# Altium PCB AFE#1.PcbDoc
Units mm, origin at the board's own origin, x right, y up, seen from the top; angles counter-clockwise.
Board outline 43.03 x 43.18 mm, 4 copper layers (Top Layer, Int1 (GND), Int2 (GND), Bottom Layer), stack 1.56 mm thick; 65 components, 51 nets, 213 pads, 60 vias.
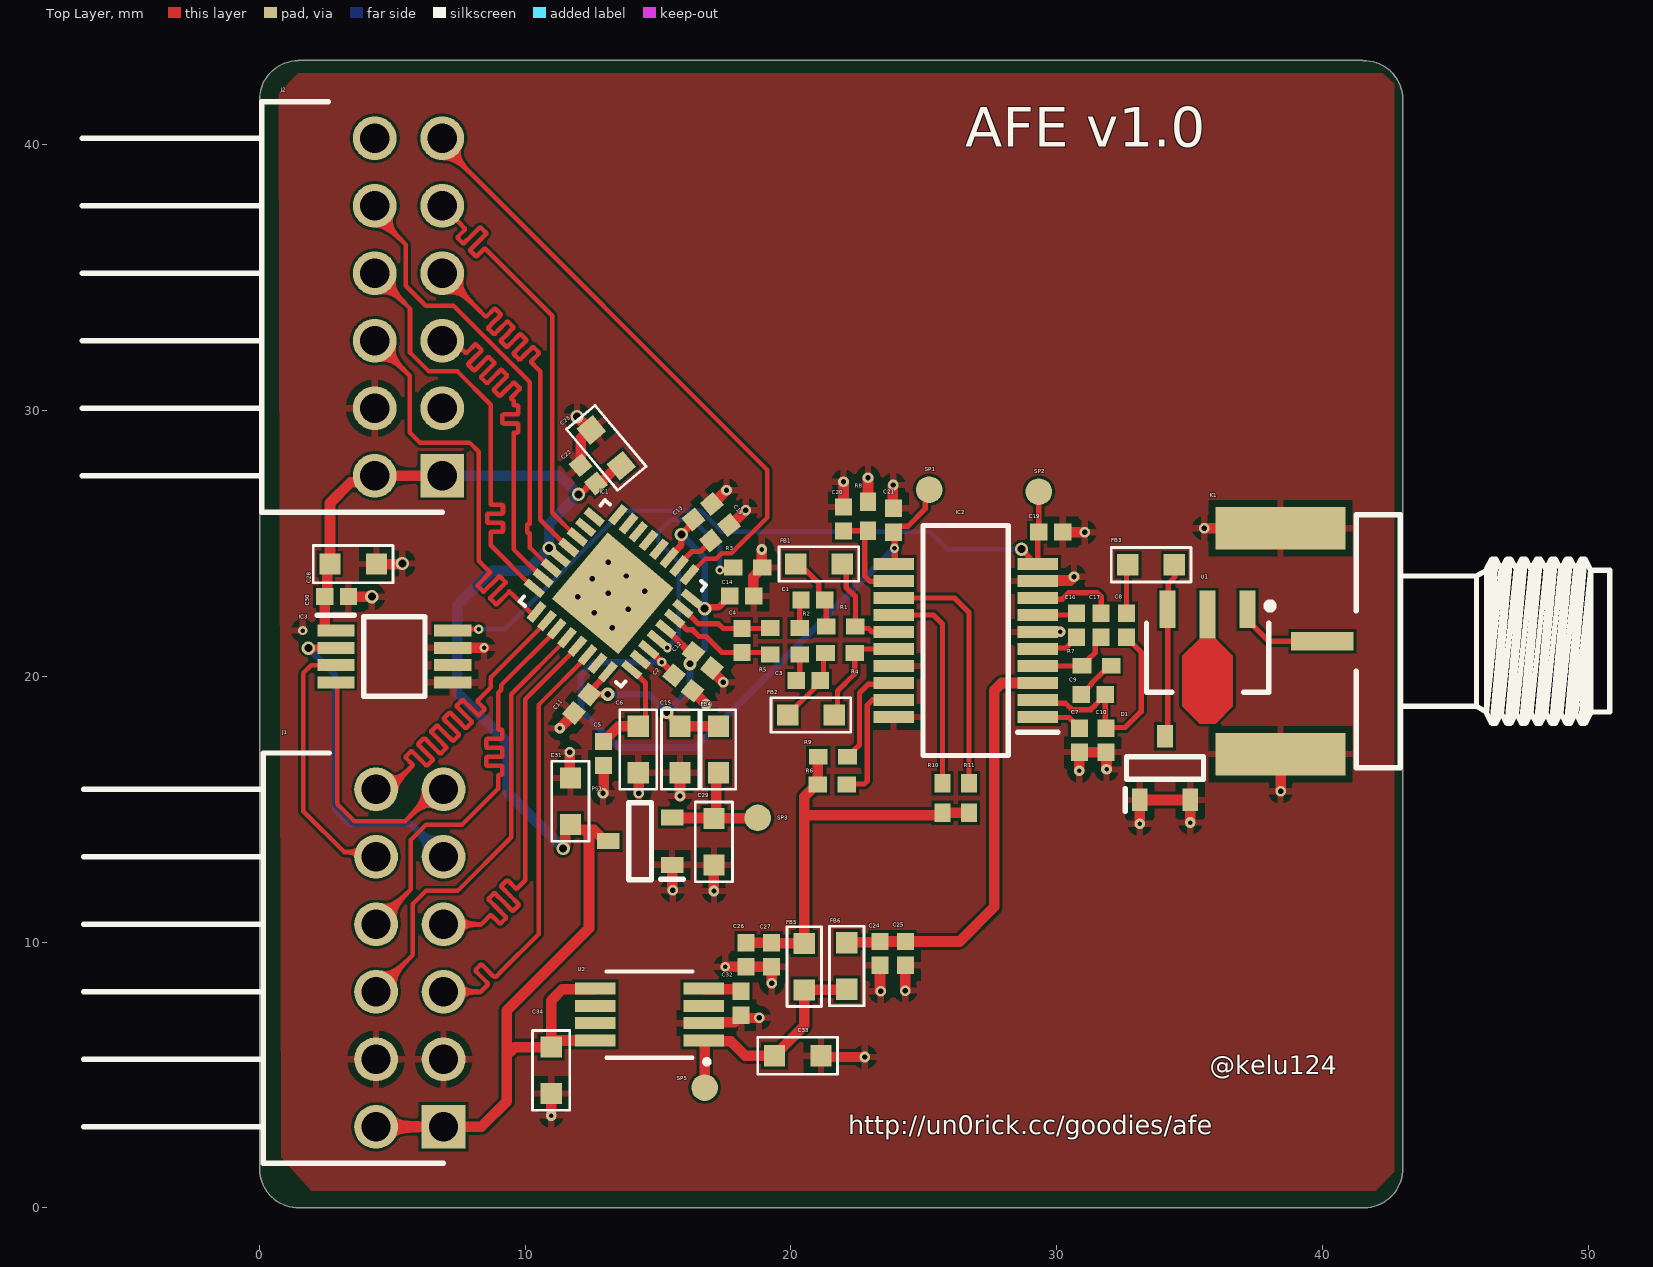
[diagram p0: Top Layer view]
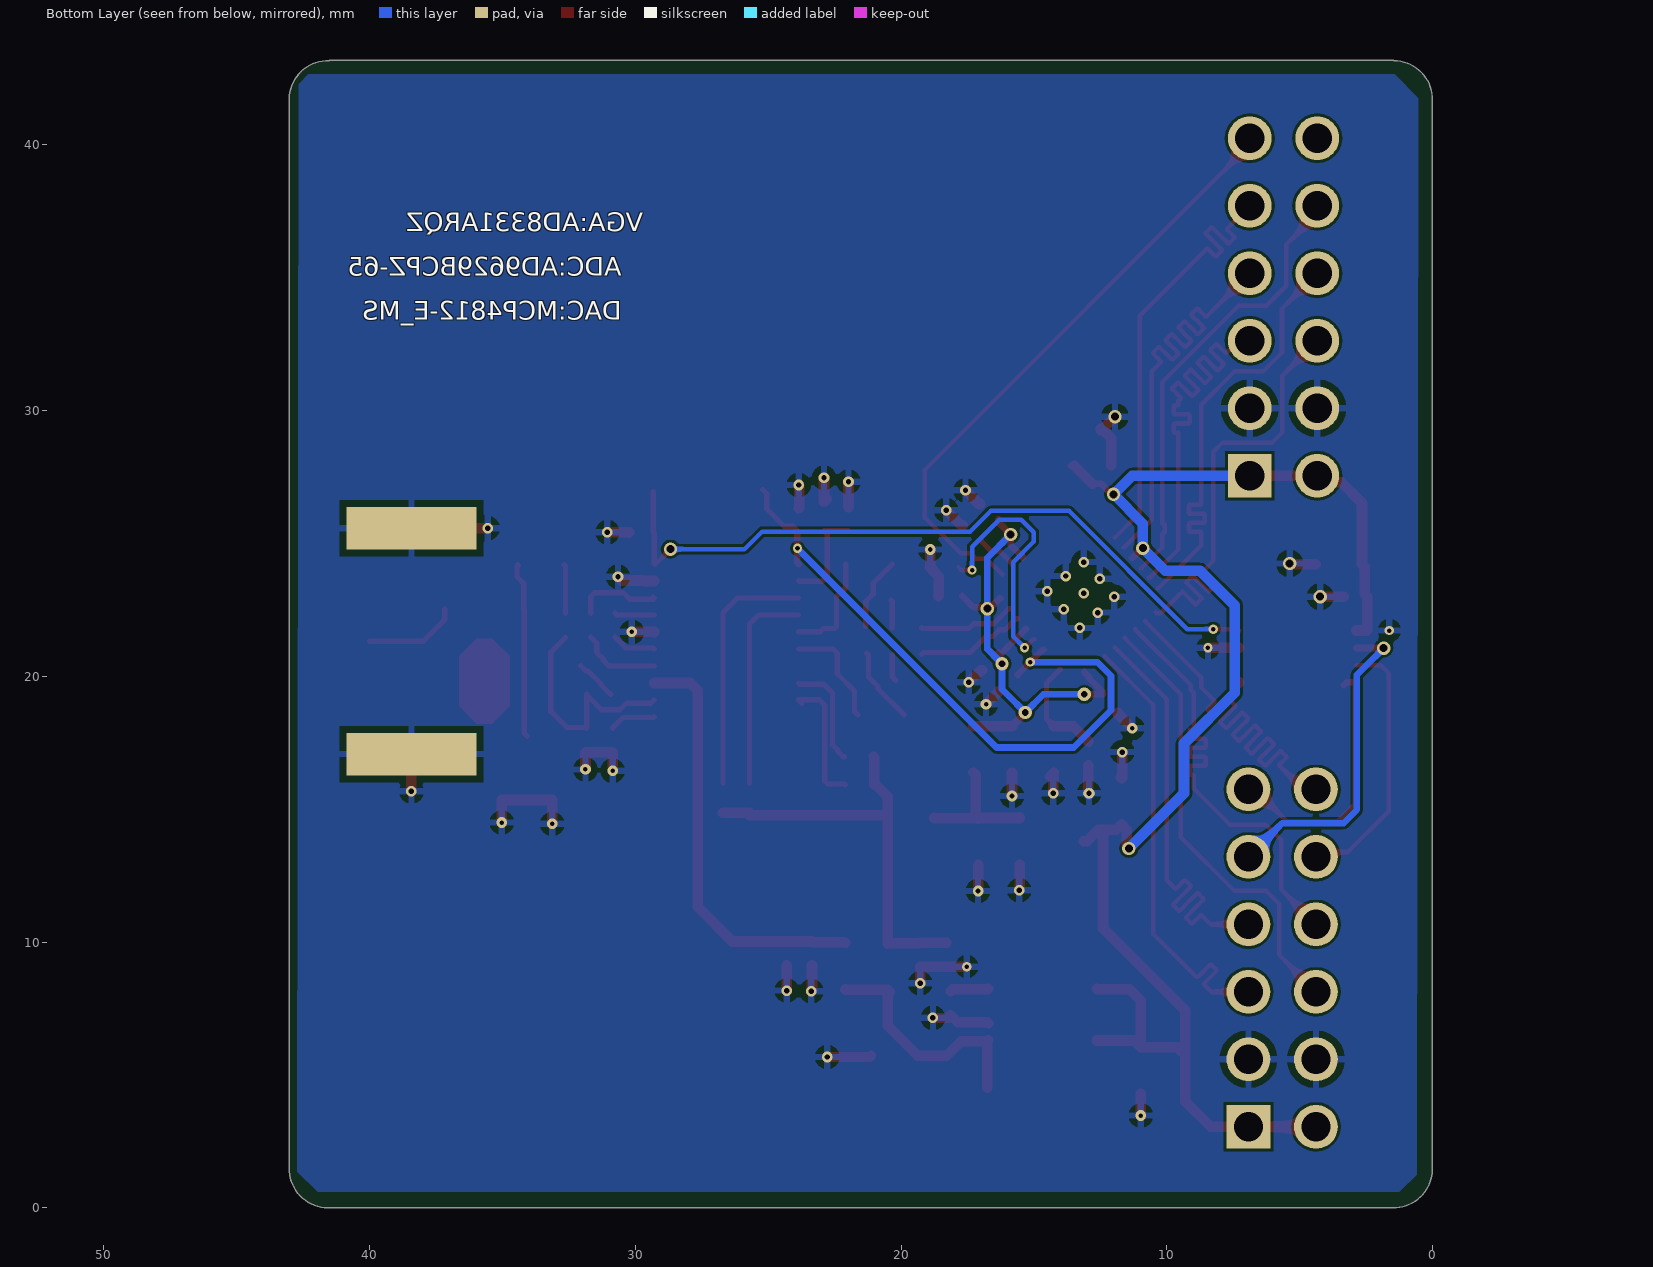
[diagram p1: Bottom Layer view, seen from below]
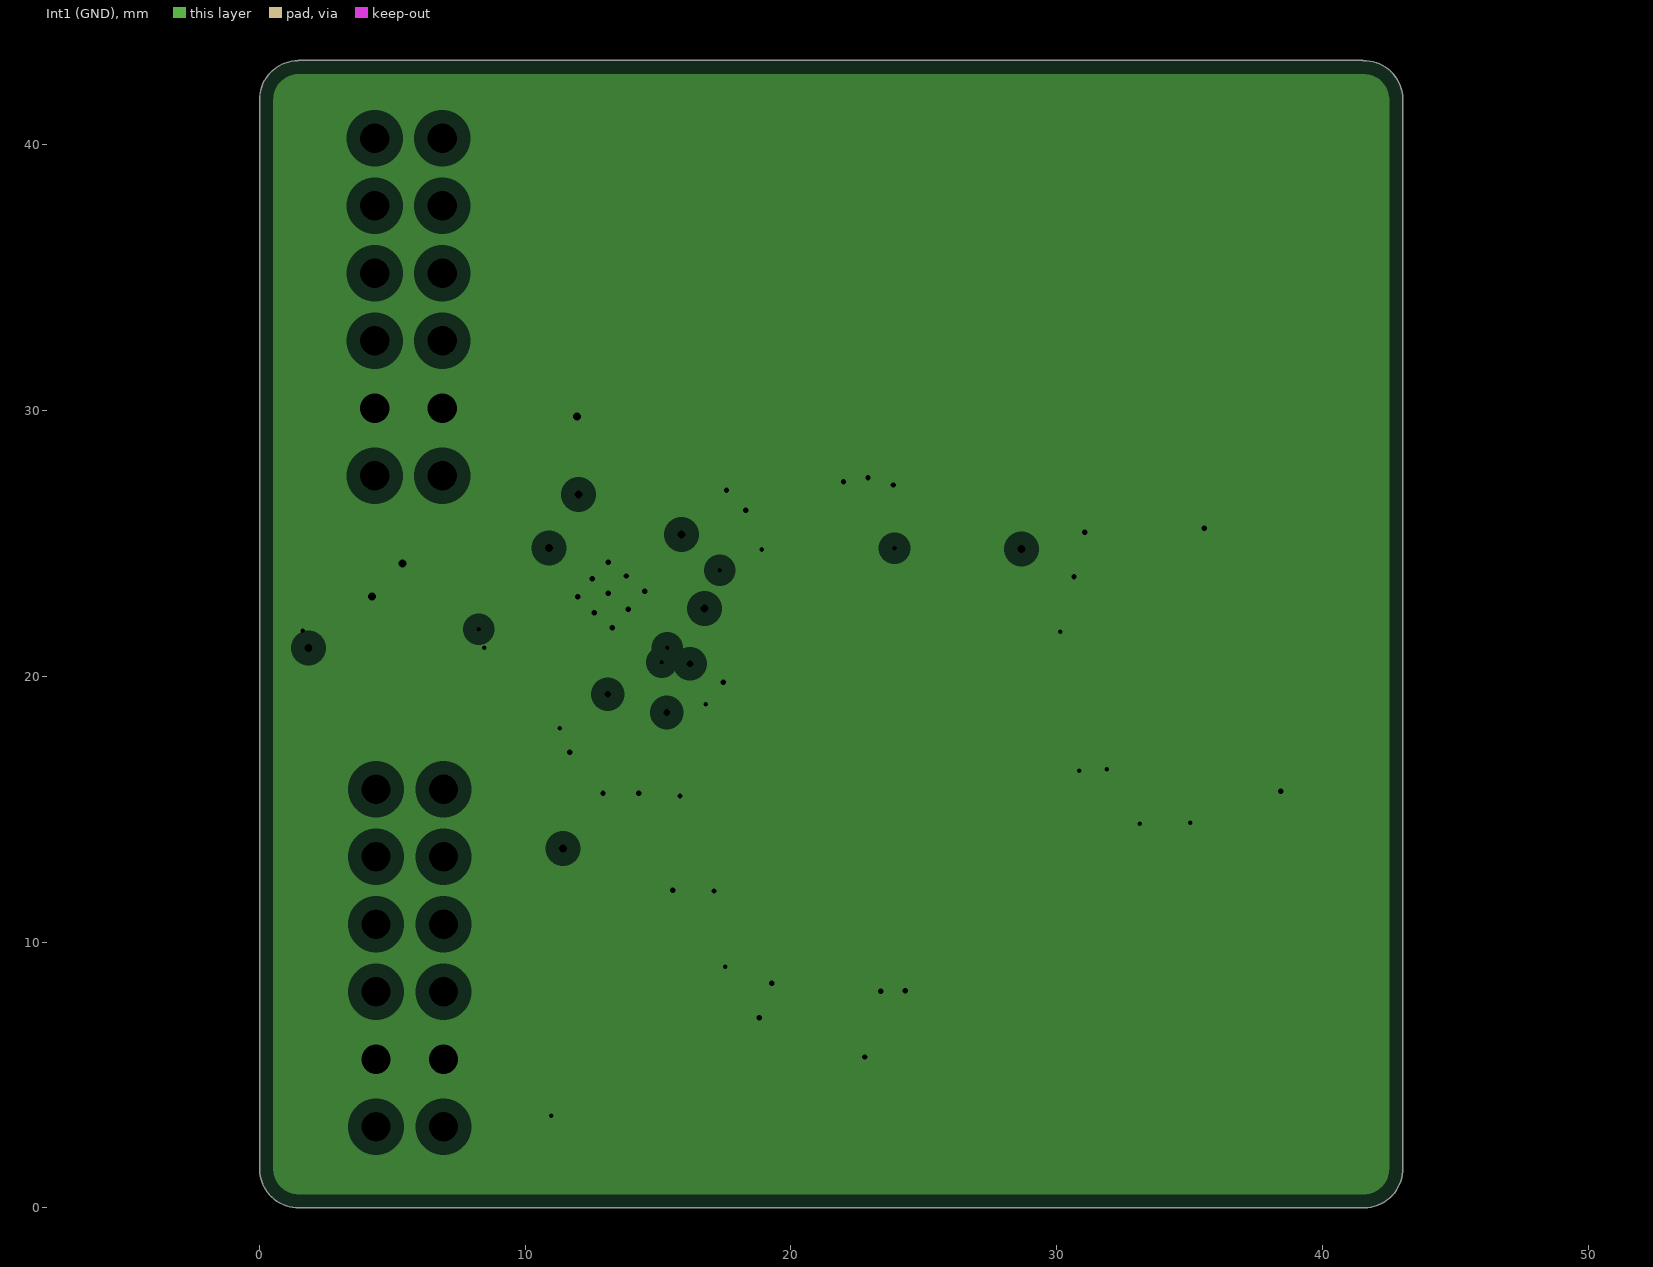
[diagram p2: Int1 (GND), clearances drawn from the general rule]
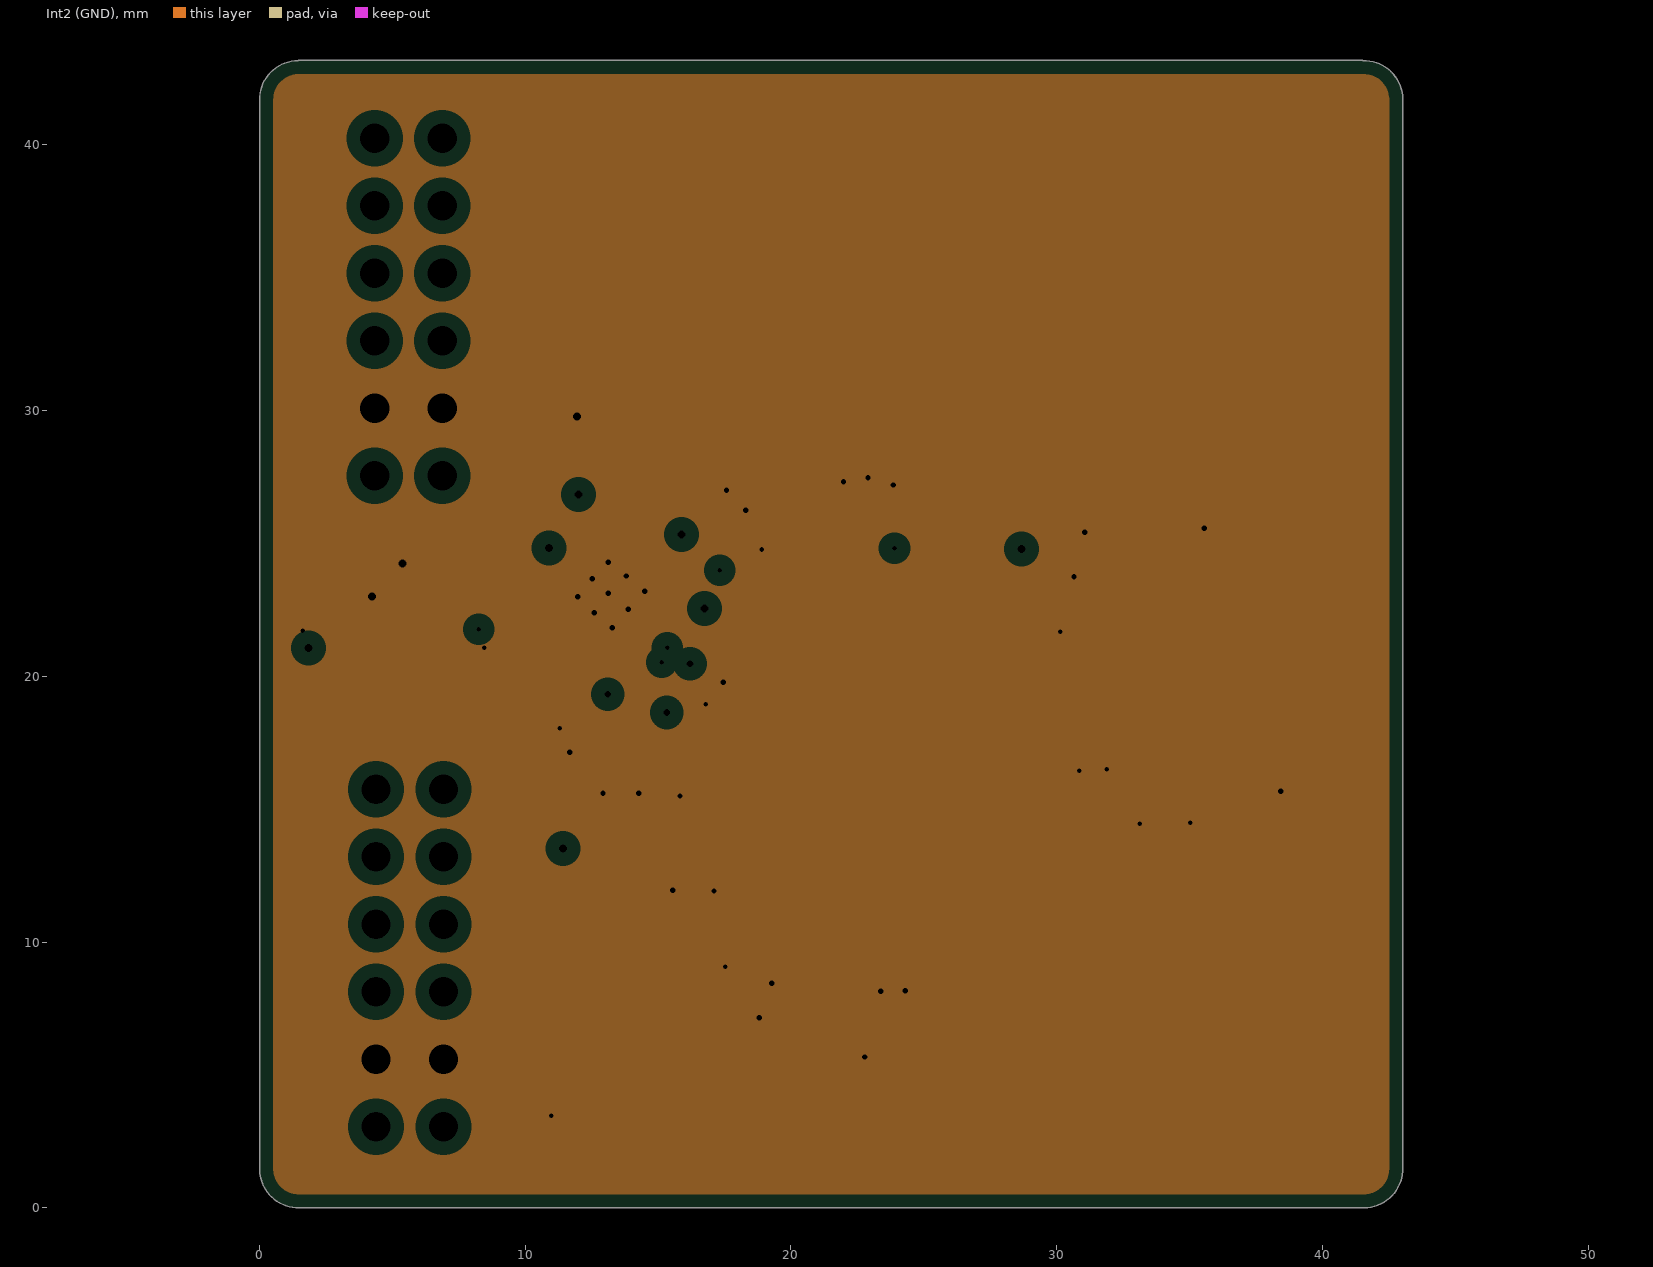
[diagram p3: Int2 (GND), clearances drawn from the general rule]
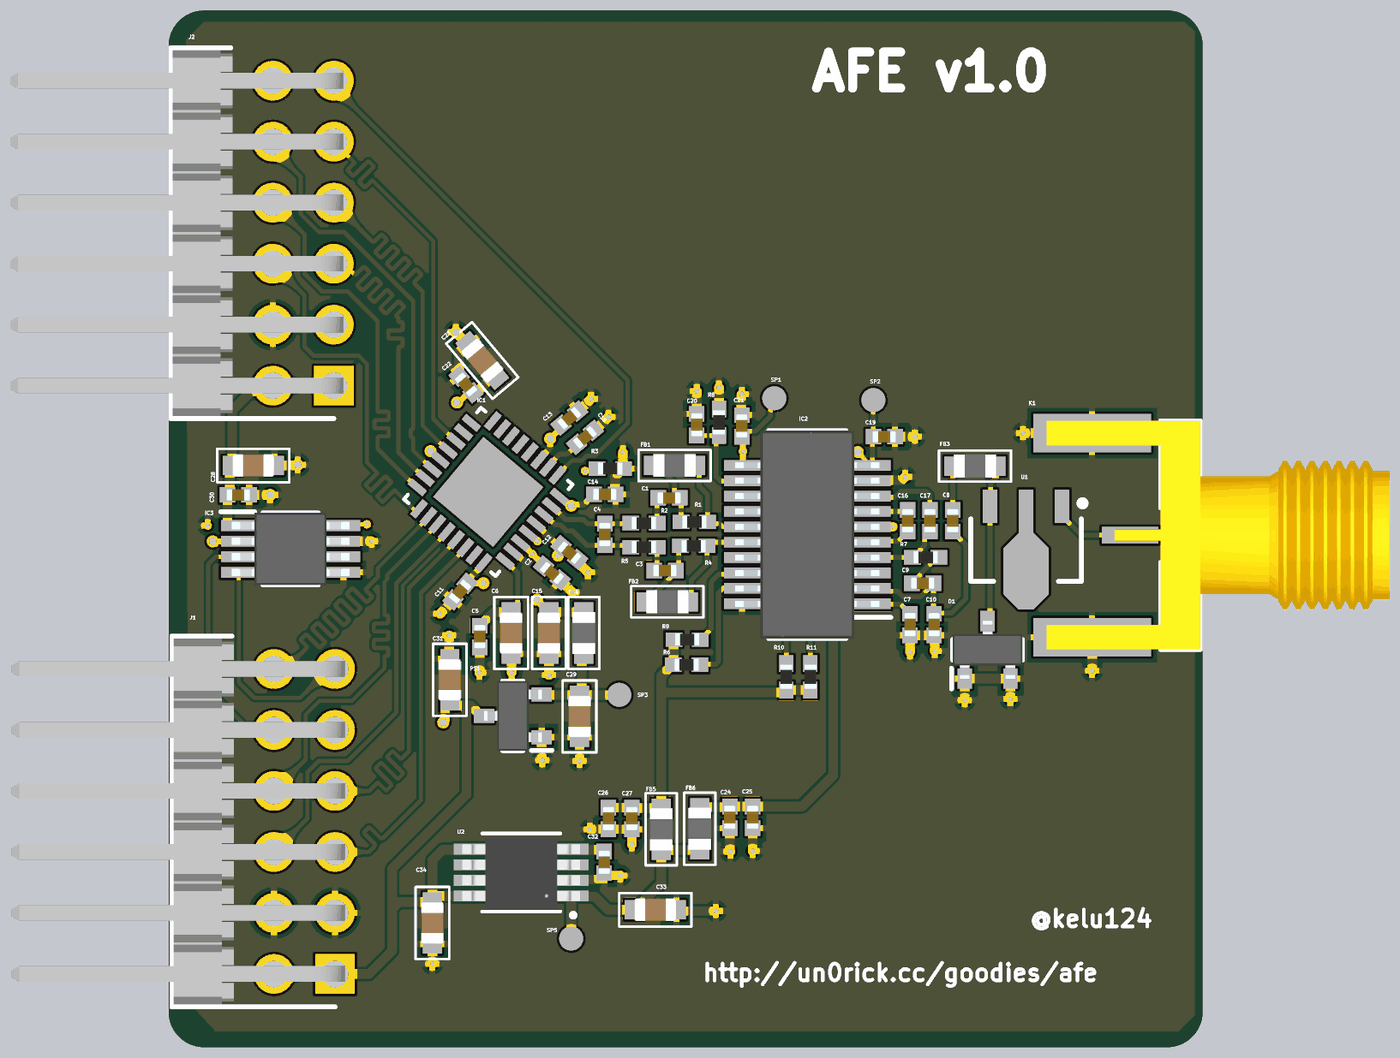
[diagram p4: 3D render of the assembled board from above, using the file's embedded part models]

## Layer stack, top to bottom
Top Solder: solder mask 0.0254, SM-001, Dk 4
Top Layer: signal copper 0.035
Dielectric 1: prepreg 0.11, PP-017, Dk 4.3
Int1 (GND): plane copper 0.035, net GND
Dielectric 3: core 1.2, Core-039, Dk 4.8
Int2 (GND): plane copper 0.035, net GND
Dielectric 5: prepreg 0.11, PP-017, Dk 4.3
Bottom Layer: signal copper 0.035
Bottom Solder: solder mask 0.0254, SM-001, Dk 4

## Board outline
0,1.45 0,41.675 cw(c1.475,41.7) 1.45,43.175 1.45,43.18 41.525,43.18 41.525,43.175 cw(c41.55,41.7) 43.025,41.725 43.025,1.5 cw(c41.55,1.475) 41.575,0 41.55,0 1.5,0 cw(c1.475,1.475)

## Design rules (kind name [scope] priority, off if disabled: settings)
Clearance [All] p1: gap=0.1 ignorepadtopadclearanceinfootprint=TRUE
ComponentClearance [All] p1: gap=0 collisioncheckmode=3 verticalgap=0 showdistances=FALSE
MatchedLengths "Schematic Matched Net Lengths" [InNetClass('Data')] p1: tolerance=0.508 checknetsindiffpair=FALSE checkdiffpairvsdiffpair=TRUE checkxsignals=TRUE checkothers=TRUE
PlaneClearance [All] p1: clearance=0.508
PlaneConnect [All] p1: planeconnectstyle=Relief reliefexpansion=0.508 reliefentries=4 reliefconductorwidth=0.254 reliefairgap=0.254
PolygonConnect [All] p1: connectstyle=Relief reliefconductorwidth=0.254 reliefentries=4 polygonreliefangle="90 Angle" airgapwidth=0.254
RoutingVias [All] p1: holewidth=0.2 width=0.4 viastyle="Through Hole" minholewidth=0.15 minwidth=0.3 maxholewidth=0.4 maxwidth=0.8
SilkToSilkClearance [All] p1: silktosilkclearance=0
SolderMaskExpansion [All] p1: expansion=0.102
UnRoutedNet [All] p1: checkbadconnections=TRUE
Width [All] p1: maxlimit=0.4 minlimit=0.15 preferedwidth=0.2
25 further rules are at their usual default settings.

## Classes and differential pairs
net class Data: D0 D1 D2 D3 D4 D5 D6 D7 D8 D9 DCO

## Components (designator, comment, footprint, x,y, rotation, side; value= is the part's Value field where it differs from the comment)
C1 "cap0402" 0402_C 20.825,22.875 r0 top value=100n
C2 "cap0402" 0402_C 15.95,19.75 r320 top value=100n
C3 "cap0402" 0402_C 20.65,19.85 r0 top value=100n
C4 "cap0402" 0402_C 18.15,21.35 r270 top value=18pf
C5 "cap0402" 0402_C 12.95,17.1 r90 top value=100n
C6 "cap0603" "SM0603 _3D_cap" 14.25,17.25 r90 top value=1u
C7 "cap0402" 0402_C 30.85,17.6 r90 top value=100n
C8 "cap0402" 0402_C 32.625,21.925 r270 top value=100n
C9 "cap0402" 0402_C 31.375,19.325 r0 top value=18n
C10 "cap0402" 0402_C 31.85,17.6 r90 top value=22pF
C11 "cap0402" 0402_C 12.125,18.975 r230 top value=100n
C12 "cap0402" 0402_C 16.675,20.6 r320 top value=100n
C13 "cap0402" 0402_C 16.675,26.2 r40 top value=100n
C14 "cap0402" 0402_C 18.15,23.025 r0 top value=100n
C15 "cap0402" "SM0603 _3D_cap" 15.825,17.25 r270 top value=10u
C16 "cap0402" 0402_C 30.75,21.925 r270 top value=100n
C17 "cap0402" 0402_C 31.675,21.925 r270 top value=100n
C18 "cap0402" 0402_C 17.325,25.4 r40 top value=100n
C19 "cap0402" 0402_C 29.775,25.425 r180 top value=1n
C20 "cap0402" 0402_C 21.975,25.925 r270 top value=100n
C21 "cap0402" 0402_C 23.85,25.875 r90 top value=100n
C22 "cap0402" 0402_C 12.375,27.6 r130 top value=100n
C23 "cap0603" "SM0603 _3D_cap" 13.05,28.6 r130 top value=10u
C24 "cap0402" 0402_C 23.35,9.575 r90 top value=1nf
C25 "cap0402" 0402_C 24.3,9.575 r90 top value=100nf
C26 "cap0402" 0402_C 18.3,9.525 r90 top value=1nf
C27 "cap0402" 0402_C 19.275,9.525 r90 top value=100nf
C28 "cap0603" "SM0603 _3D_cap" 3.525,24.225 r0 top value=10u
C29 "cap0603" "SM0603 _3D_cap" 17.1,13.775 r270 top value=4.7u
C30 "cap0402" 0402_C 2.9,23 r0 top value=100n
C31 "cap0603" "SM0603 _3D_cap" 11.7,15.3 r270 top value=4.7u
C32 "cap0402" 0402_C 18.125,7.7 r90 top value=470p
C33 "cap0603" "SM0603 _3D_cap" 20.25,5.725 r0 top value=1u
C34 "cap0603" "SM0603 _3D_cap" 10.975,5.175 r270 top value=1u
D1 "BAV99-7-F" SOT95P240X120-3N 34.075,16.55 r90 top
FB1 "75R@100MHz" SM0603_3D_res 21.05,24.225 r180 top
FB2 "75R@100MHz" SM0603_3D_res 20.75,18.55 r180 top
FB3 "75R@100MHz" SM0603_3D_res 33.55,24.2 r180 top
FB4 "75R@100MHz" SM0603_3D_res 17.275,17.25 r270 top
FB5 "75R@100MHz" SM0603_3D_res 20.5,9.075 r270 top
FB6 "75R@100MHz" SM0603_3D_res 22.1,9.1 r90 top
IC1 "AD9629BCPZ-65" QFN50P500X500X100-33N 13.3,23.125 r230 top
IC2 "AD8331ARQZ" SOP64P600X175-20N 26.575,21.35 r180 top
IC3 "MCP4812-E_MS" SOP65P490X110-8N 5.075,20.75 r0 top
J1 "90122-0126" HDRRA12W65P254_2X6_1516X250X615P 6.925,3.05 r90 top
J2 "90122-0126" HDRRA12W65P254_2X6_1516X250X615P 6.875,27.55 r90 top
K1 "SMA_Edge" AMPHENOL_132357-11 40,21.325 r180 top
PS1 "AP2127N-1.8TRG1" SOT89P240X110-3N 14.325,13.8 r180 top
R1 "100R" 0402_R 21.875,21.875 r180 top value=10k
R2 "18R" 0402_R 19.775,21.825 r180 top
R3 "10K" 0402_R 18.375,24.1 r180 top value=10k
R4 "100R" 0402_R 21.85,20.875 r180 top value=10k
R5 "18R" 0402_R 19.775,20.825 r180 top
R6 "10k" 0402_R 21.55,15.925 r0 top
R7 "280" 0402_R 31.5,20.4 r0 top
R8 "12k" 0402_R 22.9,26.025 r90 top
R9 "10k" 0402_R 21.575,16.975 r0 top
R10 "10k" 0402_R 25.7,15.425 r90 top
R11 "10k" 0402_R 26.7,15.425 r90 top
SP1 "SolderPad D1mm_round" "SolderPad_D1mm _round" 25.2,27.025 r90 top value="\"VCM\""
SP2 "SolderPad D1mm_round" "SolderPad_D1mm _round" 29.325,26.95 r90 top value="\"DG\""
SP3 "SolderPad D1mm_round" "SolderPad_D1mm _round" 18.75,14.675 r90 top value="\"+1.8V\""
SP5 "SolderPad D1mm_round" "SolderPad_D1mm _round" 16.75,4.525 r90 top value="\"+5V\""
U1 "T/R switch" SOT89-150P409X160-3N 35.675,20.725 r270 top
U2 "TC1107-5.0VUA" MSOP8_MC_MCH_ 14.675,7.275 r180 top

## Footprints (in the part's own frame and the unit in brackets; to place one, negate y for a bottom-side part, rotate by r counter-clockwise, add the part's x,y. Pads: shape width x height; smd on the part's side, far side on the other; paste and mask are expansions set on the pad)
0402_C [mm]
  rect 0.65x0.64 smd: 1(-0.45,0) 2(0.45,0)
  body extent -0.5,-0.25 0.5,0.25, height 0.56
0402_R [mm]
  rect 0.7x0.6 smd: 1(-0.55,0) 2(0.55,0)
  body extent -0.5,-0.25 0.5,0.25, height 0.35
AMPHENOL_132357-11 [mm]
  rect 2.35x0.7 smd: 1(0,0)
  rect 4.9x1.6 smd: 2(1.575,4.25) 2(1.575,-4.25)
  rect 4.9x1.6 smd far side: 2(1.575,4.25) 2(1.575,-4.25)
  silkscreen extent -10.81,-4.76 -1.28,4.76, body extent -10.8,-4.76 3.48,4.76, height 4.08
HDRRA12W65P254_2X6_1516X250X615P [mm]
  rect 1.65x1.65 hole 1.1: 1(0,0)
  round 1.65 hole 1.1: 2(0,2.54) 3(2.54,0) 4(2.54,2.54) 5(5.08,0) 6(5.08,2.54) 7(7.62,0) 8(7.62,2.54) 9(10.16,0) 10(10.16,2.54) 11(12.7,0) 12(12.7,2.54)
  silkscreen extent -1.37,0 14.07,13.54, body extent -1.27,-0.4 13.97,13.47, height 6.16
MSOP8_MC_MCH_ [mil]
  rect 60x18 smd paste+0 mask+0: 1(-80.5,38.39) 2(-80.5,12.8) 3(-80.5,-12.8) 4(-80.5,-38.39) 5(80.5,-38.39) 6(80.5,-12.8) 7(80.5,12.8) 8(80.5,38.39)
  silkscreen extent -87,-64 64,72, body extent -96,-59 96,59, height 43
QFN50P500X500X100-33N [mil]
  rect 32x12 smd: 1(-94,69) 2(-94,49) 3(-94,30) 4(-94,10) 5(-94,-10) 6(-94,-30) 7(-94,-49) 8(-94,-69) 17(94,-69) 18(94,-49) 19(94,-30) 20(94,-10) 21(94,10) 22(94,30) 23(94,49) 24(94,69)
  rect 12x32 smd: 9(-69,-94) 10(-49,-94) 11(-30,-94) 12(-10,-94) 13(10,-94) 14(30,-94) 15(49,-94) 16(69,-94) 25(69,94) 26(49,94) 27(30,94) 28(10,94) 29(-10,94) 30(-30,94) 31(-49,94) 32(-69,94)
  rect 128x128 smd: 33(0,0)
  silkscreen extent -98,-98 98,98
"SM0603 _3D_cap" [mm]
  rect 0.8x0.8 smd: 1(-0.875,0) 2(0.875,0)
  silkscreen extent -1.5,-0.7 1.5,0.7, body extent -0.87,-0.47 0.88,0.48, height 0.87
SM0603_3D_res [mm]
  rect 0.8x0.8 smd: 1(-0.875,0) 2(0.875,0)
  silkscreen extent -1.5,-0.65 1.5,0.65, body extent -0.87,-0.47 0.88,0.48, height 0.55
"SolderPad_D1mm _round" [mm]
  round 1 smd: 1(0,0)
SOP64P600X175-20N [mm]
  rect 1.52x0.44 smd: 1(-2.715,2.88) 2(-2.715,2.24) 3(-2.715,1.6) 4(-2.715,0.96) 5(-2.715,0.32) 6(-2.715,-0.32) 7(-2.715,-0.96) 8(-2.715,-1.6) 9(-2.715,-2.24) 10(-2.715,-2.88) 11(2.715,-2.88) 12(2.715,-2.24) 13(2.715,-1.6) 14(2.715,-0.96) 15(2.715,-0.32) 16(2.715,0.32) 17(2.715,0.96) 18(2.715,1.6) 19(2.715,2.24) 20(2.715,2.88)
  silkscreen extent -3.47,-4.33 1.61,4.33, body extent -3,-4.33 3,4.33, height 1.75
SOP65P490X110-8N [mm]
  rect 1.4x0.45 smd: 1(-2.2,0.975) 2(-2.2,0.325) 3(-2.2,-0.325) 4(-2.2,-0.975) 5(2.2,-0.975) 6(2.2,-0.325) 7(2.2,0.325) 8(2.2,0.975)
  silkscreen extent -2.9,-1.5 1.15,1.55, body extent -2.45,-1.5 2.45,1.5, height 1.1
SOT89-150P409X160-3N [mm]
  rect 1.4x0.6 smd: 1(-1.8,1.5) 3(-1.8,-1.5)
  rect 1.8x0.6 smd: 2(-1.6,0)
  Top Layer region: -0.7,0.3 -0.05,0.95 1.85,0.95 2.5,0.3 2.5,-0.3 1.85,-0.95 -0.05,-0.95 -0.7,-0.3
  silkscreen extent -2.05,-2.3 1.32,2.48, body extent -1.28,-2.3 1.32,2.3, height 1.6
SOT89P240X110-3N [mm]
  rect 0.85x0.6 smd: 1(-1.2,0.89) 2(-1.2,-0.89) 3(1.2,0)
  silkscreen extent -1.63,-1.45 0.43,1.45, body extent -1.2,-1.45 1.2,1.45, height 1.1
SOT95P240X120-3N [mm]
  rect 0.85x0.6 smd: 1(-1.2,0.95) 2(-1.2,-0.95) 3(1.2,0)
  silkscreen extent -1.63,-1.45 0.43,1.5, body extent -1.2,-1.45 1.2,1.45, height 1.2

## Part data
C1 C2 C3 C4 C5 C7 C8 C9 C10 C11 C12 C13 C14 C15 C16 C17 C18 C19 C20 C21 C22 C25 C27 C30 C32: library part cap0603, "Capacitor  0402 inch"
C6 C23 C28 C29 C31 C33 C34: "Capacitor  0603 inch"
C24 C26: library part cap0603, "Capacitor  0603 inch"
D1: "Diode", Manufacturer_Name="Diodes Inc.", Mouser Part Number=621-BAV99-F
FB1 FB2 FB3 FB4 FB5 FB6: "chip inductance 0603", Case=0805, Manufacturer=MURATA, Manufacturer Part Number=BLM21BB750SN1D, Part Number=IND0805_MURATA_BLM21BB750SN1D, Power=700mA, Resistance=0.16R, Tolerance=±25%
IC1: "Integrated Circuit", Manufacturer_Name="Analog Devices", Mouser Part Number=584-AD9629BCPZ-65
IC2: "Integrated Circuit", Manufacturer_Name="Analog Devices", Mouser Part Number=584-AD8331ARQZ
IC3: "Integrated Circuit", Arrow Part Number=MCP4812-E/MS, Manufacturer_Name=Microchip, Mouser Part Number=579-MCP4812-E/MS
J1 J2: "Connector", Manufacturer_Name=Molex, Mouser Part Number=538-90122-0126
PS1: library part AP2127N-3.3TRG1, "Power Supply", Manufacturer_Name="Diodes Inc.", Mouser Part Number=621-AP2127N-3.3TRG1
R1 R3 R4: library part RC0402FR-0710KL, "RES 10K OHM 1/16W 0402 SMD", Package / Case="0402 (1005 Metric)", Power (Watts)="0.063W, 1/16W"
R2 R5: library part RC0402FR-0710KL, "RES 18 OHM 1/16W 0402 SMD", Package / Case="0402 (1005 Metric)", Power (Watts)="0.063W, 1/16W"
R6 R9 R10 R11: library part RC0402FR-0710KL, "RES 10K OHM 1/16W 1% 0402 SMD", Package / Case="0402 (1005 Metric)", Power (Watts)="0.063W, 1/16W", Resistance (Ohms)=280
R7: library part RC0402FR-0710KL, "RES 280 OHM 1/16W 0402 SMD", Package / Case="0402 (1005 Metric)", Power (Watts)="0.063W, 1/16W"
R8: library part RC0402FR-0710KL, "RES 12K OHM 1/16W 0402 SMD", Package / Case="0402 (1005 Metric)", Power (Watts)="0.063W, 1/16W"
SP1 SP2 SP3 SP5: "for finger touch"
U1: library part MD0100N8-G
U2: "No Description Available", Mfr_Name=Microchip

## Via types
v1: diameter 0.4, hole 0.2, Top Layer to Bottom Layer, 30 vias
v2: diameter 0.5, hole 0.3, Top Layer to Bottom Layer, 10 vias
v3: diameter 0.4, hole 0.17, Top Layer to Bottom Layer, 9 vias
v4: diameter 0.35, hole 0.17, Top Layer to Bottom Layer, 8 vias
v5: diameter 0.5, hole 0.254, Top Layer to Bottom Layer, 3 vias

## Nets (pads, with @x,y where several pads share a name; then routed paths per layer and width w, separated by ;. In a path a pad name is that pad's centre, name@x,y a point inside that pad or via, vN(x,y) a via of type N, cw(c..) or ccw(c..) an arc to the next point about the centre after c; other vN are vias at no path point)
5VLNA: C24.2 C25.2 FB6.2 IC2.3 | length 16
  Top Layer w0.4: FB6.2 22.125,10 23.325,10 C24.2 C25.2 26.35,10.025 27.65,11.325 27.65,19.47 27.93,19.75 IC2.3
5VVGA: C26.2 C27.2 FB5.1 R6.1 R9.1 R10.1 R11.1 | length 15.7
  Top Layer w0.4: C26.2 C27.2 19.288,9.962 20.488,9.962 FB5.1 20.5,14.75 ; R9.1 21.013,16.963 21.013,15.938 R6.1 20.95,15.925 20.5,15.475 20.5,14.75 ; R10.1@25.7,14.775 20.525,14.775 20.5,14.75 ; R10.1 R11.1
+1V8: C29.1 FB4.2 PS1.2 SP3.1 | length 5
  Top Layer w0.4: PS1.2 15.545,14.67 17.08,14.67 C29.1 C29.1@17.113,14.662 ; FB4.2 17.188,16.287 17.188,14.737 C29.1@17.113,14.662 ; SP3.1 18.737,14.662 C29.1@17.113,14.662
+1V8f: C11.1 C12.1 C13.1 C14.1 C15.1 FB4.1 IC1.3 IC1.24 IC1.29 IC1.32 | length 19.7
  Top Layer w0.25: v5(13.1,19.325) 13.098,19.323 12.417,19.323 C11.1 12.414,19.414 12.931,19.931 12.931,19.98 12.925,19.987 IC1.24 ; IC1.29 15.315,21.785 15.315,21.774 16.255,20.833 16.255,20.814 C12.1 16.33,20.605 v5(16.2,20.475) ; IC1.3 15.418,24.493 15.875,24.95 v2(15.875,25.338) 16.33,25.794 C13.1 ; IC1.32 16.292,22.933 16.675,22.55 16.723,22.598 17.268,22.598 17.695,23.025 C14.1
  Top Layer w0.3: v5(15.325,18.638) 15.325,18.625 C15.1
  Top Layer w0.4: C15.1 FB4.1
  Bottom Layer w0.25: v5(13.1,19.325) 14.638,19.325 v5(15.325,18.638) 16.2,19.513 v5(16.2,20.475) 16.75,21.025 v2(16.75,22.55) 16.75,24.463 v2(15.875,25.338)
+3V3: C22.1 C23.1 C28.1 C30.1 C31.2 C34.1 IC1.13 IC3.1 J1.1 J1.2 J2.1 J2.2 PS1.3 U2.5 U2.8 | length 62.4
  Top Layer w0.25: v2(10.9,24.825) 10.925,24.825 11.285,24.465 IC1.13 IC1.13@11.273,24.5 ; v2(12,26.85) 12.068,26.85 12.473,27.255 C22.1 C22.1@12.801,27.255 ; C23.1@13.475,27.93 C23.1
  Top Layer w0.4: IC3.1 2.475,21.725 2.45,21.75 C30.1 2.55,23.1 2.55,24.125 C28.1 2.65,26.525 3.436,27.311 4.096,27.311 J2.2 J2.1 ; J1.2 J1.1 8.35,3.05 9.3,4 9.3,5.75 ; v2(11.425,13.525) 11.425,13.552 11.5,13.627 11.5,14.225 C31.2 11.9,14.225 12.245,14.225 ; U2.8 11.225,6.3 C34.1 ; U2.5 12.602,8.221 11.396,8.221 10.975,7.8 C34.1 ; C22.1@12.801,27.255 C23.1@13.475,27.93 ; PS1.3 13,13.8 12.575,14.225 12.245,14.225 ; 9.3,5.75 9.3,7.425 12.4,10.525 12.4,14.069 12.245,14.225 ; 9.3,5.75 9.6,6.05 C34.1
  Bottom Layer w0.4: J2.1 11.3,27.55 v2(12,26.85) 10.9,25.75 v2(10.9,24.825) 10.05,23.975 8.75,23.975 7.441,22.666 7.441,19.384 9.35,17.475 9.35,15.6 v2(11.425,13.525)
+5V: C33.1 FB5.2 FB6.1 SP5.1 U2.1 | length 9.3
  Top Layer w0.4: U2.1 16.748,6.271 U2.1@16.75,6.271 ; SP5.1 U2.1@16.75,6.271 ; FB6.1 22.087,8.213 20.513,8.213 FB5.2 20.425,8.125 20.5,8.05 20.5,6.85 C33.1 18.275,5.725 17.729,6.271 U2.1@16.75,6.271
CLK+: IC1.1 J2.11 | length 23.2
  Top Layer w0.17: J2.11 6.875,40 19.1,27.775 19.1,25.975 17.758,24.633 17.39,24.633 17.189,24.432 16.782,24.432 IC1.1
CS: IC3.2 J1.9 | length 12.5
  Top Layer w0.25: v2@1.95,20.95 v2(1.836,21.064) 1.842,21.069 2.869,21.069 IC3.2
  Bottom Layer w0.25: v2(1.836,21.064) 2.85,20.05 2.85,14.975 3.35,14.475 5.66,14.475 J1.9
D0: IC1.11 J2.9 | length 17.1
  Top Layer w0.17: J2.9 7.442,37.143 7.511,37.074 7.715,36.87 cw(c7.679,36.834) 7.715,36.798 7.47,36.553 ccw(c7.506,36.517) 7.47,36.481 7.638,36.312 ccw(c7.674,36.348) 7.71,36.312 7.991,36.594 8.273,36.875 cw(c8.309,36.839) 8.345,36.875 8.513,36.707 cw(c8.477,36.67) 8.513,36.634 8.232,36.353 7.951,36.072 ccw(c7.987,36.036) 7.951,36 8.119,35.831 ccw(c8.155,35.868) 8.191,35.831 8.436,36.077 cw(c8.472,36.041) 8.508,36.077 8.592,35.993 11.013,33.573 11.013,26.16 11.929,25.243 IC1.11
D1: IC1.12 J2.7 | length 17.2
  Top Layer w0.17: J2.7 8.235,33.81 8.485,33.56 ccw(c8.521,33.596) 8.558,33.56 8.814,33.816 cw(c8.85,33.78) 8.886,33.816 9.055,33.648 cw(c9.019,33.612) 9.055,33.576 8.762,33.283 8.622,33.143 ccw(c8.658,33.107) 8.622,33.071 8.79,32.902 ccw(c8.826,32.938) 8.862,32.902 9.002,33.043 9.295,33.336 cw(c9.331,33.3) 9.367,33.336 9.536,33.167 cw(c9.5,33.131) 9.536,33.095 9.243,32.802 9.102,32.662 ccw(c9.139,32.626) 9.102,32.59 9.271,32.422 ccw(c9.307,32.458) 9.343,32.422 9.483,32.562 9.776,32.855 cw(c9.812,32.819) 9.848,32.855 10.016,32.686 cw(c9.98,32.65) 10.016,32.614 9.724,32.321 9.583,32.181 ccw(c9.619,32.145) 9.583,32.109 9.752,31.941 ccw(c9.788,31.977) 9.824,31.941 9.964,32.081 10.257,32.374 cw(c10.293,32.338) 10.329,32.374 10.497,32.206 cw(c10.461,32.17) 10.497,32.133 10.24,31.877 ccw(c10.277,31.841) 10.24,31.805 10.445,31.6 10.565,31.48 10.565,25.892 11.603,24.854 IC1.12
D2: IC1.14 J2.10 | length 17.1
  Top Layer w0.17: J2.10 4.335,37.415 5.5,36.25 5.5,34.7 6.25,33.95 7.3,33.95 10.177,31.073 10.177,26.325 10.177,25.786 cw(c10.126,25.786) 10.126,25.735 ccw(c10.126,25.684) 10.075,25.684 10.075,25.446 ccw(c10.126,25.446) 10.126,25.395 cw(c10.126,25.344) 10.177,25.344 10.177,25.225 10.177,24.849 10.95,24.076 IC1.14
D3: IC1.15 J2.5 | length 17.3
  Top Layer w0.17: J2.5 7.275,32.63 7.63,32.275 7.65,32.275 7.734,32.191 ccw(c7.77,32.227) 7.806,32.191 8.093,32.478 cw(c8.129,32.442) 8.165,32.478 8.334,32.31 cw(c8.298,32.274) 8.334,32.238 8.011,31.914 7.875,31.779 ccw(c7.911,31.743) 7.875,31.707 8.043,31.538 ccw(c8.079,31.574) 8.115,31.538 8.251,31.674 8.574,31.997 cw(c8.61,31.961) 8.646,31.997 8.815,31.829 cw(c8.779,31.793) 8.815,31.757 8.491,31.434 8.356,31.298 ccw(c8.392,31.262) 8.356,31.226 8.524,31.058 ccw(c8.56,31.094) 8.596,31.058 8.732,31.193 9.055,31.516 cw(c9.091,31.48) 9.127,31.516 9.295,31.348 cw(c9.259,31.312) 9.295,31.276 8.972,30.953 8.837,30.817 ccw(c8.873,30.781) 8.837,30.745 9.005,30.577 ccw(c9.041,30.613) 9.077,30.577 9.213,30.712 9.536,31.035 cw(c9.572,30.999) 9.608,31.035 9.776,30.867 cw(c9.74,30.831) 9.776,30.795 9.489,30.508 ccw(c9.525,30.472) 9.489,30.436 9.559,30.366 9.559,30.247 ccw(c9.61,30.247) 9.61,30.196 9.686,30.196 cw(c9.686,30.145) 9.737,30.145 9.737,29.907 cw(c9.686,29.907) 9.686,29.856 9.559,29.856 9.19,29.856 ccw(c9.19,29.805) 9.139,29.805 9.139,29.567 ccw(c9.19,29.567) 9.19,29.516 9.559,29.516 9.686,29.516 cw(c9.686,29.465) 9.737,29.465 9.737,29.227 cw(c9.686,29.227) 9.686,29.176 9.61,29.176 ccw(c9.61,29.125) 9.559,29.125 9.559,28.45 9.559,24.787 10.64,23.706 IC1.15
D4: IC1.16 J2.8 | length 16.9
  Top Layer w0.17: J2.8 5.662,33.843 5.662,32.187 6.375,31.475 7.45,31.475 8.7,30.225 8.7,28 8.7,26.511 ccw(c8.751,26.511) 8.751,26.46 9.112,26.46 cw(c9.112,26.409) 9.163,26.409 9.163,26.171 cw(c9.112,26.171) 9.112,26.12 8.7,26.12 8.616,26.12 ccw(c8.616,26.069) 8.565,26.069 8.565,25.831 ccw(c8.616,25.831) 8.616,25.78 8.7,25.78 9.112,25.78 cw(c9.112,25.729) 9.163,25.729 9.163,25.491 cw(c9.112,25.491) 9.112,25.44 8.751,25.44 ccw(c8.751,25.389) 8.7,25.389 8.7,25.1 8.7,24.93 10.313,23.317 IC1.16
D5: IC1.17 J2.6 | length 17.1
  Top Layer w0.17: J2.6 5.65,31.315 5.65,29.175 6.025,28.8 7.9,28.8 8.25,28.45 8.25,24.35 8.45,24.15 8.684,23.916 8.2,23.433 ccw(c8.212,23.421) 8.2,23.409 8.417,23.193 ccw(c8.429,23.205) 8.441,23.193 8.924,23.676 9.013,23.765 cw(c9.025,23.753) 9.037,23.765 9.254,23.549 cw(c9.242,23.537) 9.254,23.525 9.164,23.436 8.681,22.952 ccw(c8.693,22.94) 8.681,22.928 8.897,22.712 ccw(c8.909,22.724) 8.921,22.712 9.405,23.195 9.525,23.075 10.075,22.525 10.228,22.372 10.372,22.372 IC1.17
D6: IC1.18 J1.12 | length 17.3
  Top Layer w0.17: J1.12 4.668,16.033 5.153,16.033 5.66,16.54 5.744,16.624 ccw(c5.708,16.66) 5.744,16.697 5.515,16.926 cw(c5.551,16.962) 5.515,16.998 5.683,17.166 cw(c5.719,17.13) 5.755,17.166 6.02,16.901 6.257,16.664 ccw(c6.293,16.7) 6.329,16.664 6.497,16.832 ccw(c6.461,16.869) 6.497,16.905 6.261,17.141 5.996,17.407 cw(c6.032,17.443) 5.996,17.479 6.164,17.647 cw(c6.2,17.611) 6.236,17.647 6.501,17.382 6.766,17.116 ccw(c6.802,17.153) 6.839,17.116 7.007,17.285 ccw(c6.971,17.321) 7.007,17.357 6.742,17.622 6.476,17.887 cw(c6.512,17.923) 6.476,17.959 6.645,18.128 cw(c6.681,18.092) 6.717,18.128 6.982,17.863 7.247,17.597 ccw(c7.283,17.633) 7.319,17.597 7.488,17.766 ccw(c7.452,17.802) 7.488,17.838 7.222,18.103 6.957,18.368 cw(c6.993,18.404) 6.957,18.44 7.125,18.609 cw(c7.162,18.573) 7.198,18.609 7.463,18.343 7.728,18.078 ccw(c7.764,18.114) 7.8,18.078 7.969,18.246 ccw(c7.932,18.282) 7.969,18.319 7.703,18.584 7.438,18.849 cw(c7.474,18.885) 7.438,18.921 7.606,19.089 cw(c7.642,19.053) 7.678,19.089 7.944,18.824 8.209,18.559 ccw(c8.245,18.595) 8.281,18.559 8.449,18.727 ccw(c8.413,18.763) 8.449,18.799 8.22,19.029 cw(c8.256,19.065) 8.22,19.101 8.397,19.278 8.71,19.591 8.71,19.963 10.812,22.065 IC1.18
D7: IC1.19 J1.8 | length 17.2
  Top Layer w0.17: J1.8 5.7,11.985 5.7,13.85 6.275,14.425 7.625,14.425 8.98,15.78 8.98,15.95 8.98,16.239 cw(c9.031,16.239) 9.031,16.29 9.088,16.29 ccw(c9.088,16.341) 9.139,16.341 9.139,16.579 ccw(c9.088,16.579) 9.088,16.63 8.98,16.63 8.59,16.63 cw(c8.59,16.681) 8.539,16.681 8.539,16.919 cw(c8.59,16.919) 8.59,16.97 8.98,16.97 9.088,16.97 ccw(c9.088,17.021) 9.139,17.021 9.139,17.259 ccw(c9.088,17.259) 9.088,17.31 8.98,17.31 8.59,17.31 cw(c8.59,17.361) 8.539,17.361 8.539,17.599 cw(c8.59,17.599) 8.59,17.65 8.98,17.65 9.088,17.65 ccw(c9.088,17.701) 9.139,17.701 9.139,17.939 ccw(c9.088,17.939) 9.088,17.99 9.031,17.99 cw(c9.031,18.041) 8.98,18.041 8.98,18.675 8.98,19.38 9.1,19.5 9.1,19.673 11.182,21.754 IC1.19
D8: IC1.20 J1.6 | length 17
  Top Layer w0.17: J1.6 5.775,9.52 5.775,11.45 6.25,11.925 7.45,11.925 9.475,13.95 9.475,19.332 11.571,21.428 IC1.20
D9: IC1.21 J1.7 | length 17.5
  Top Layer w0.17: J1.7@7.208,10.387 J1.7 8.345,10.67 8.465,10.79 8.67,10.995 cw(c8.706,10.958) 8.742,10.995 9.017,10.72 ccw(c9.053,10.756) 9.089,10.72 9.257,10.888 ccw(c9.221,10.924) 9.257,10.96 8.946,11.271 8.635,11.582 cw(c8.671,11.618) 8.635,11.654 8.803,11.823 cw(c8.839,11.786) 8.875,11.823 9.186,11.511 9.498,11.2 ccw(c9.534,11.236) 9.57,11.2 9.738,11.369 ccw(c9.702,11.405) 9.738,11.441 9.427,11.752 9.116,12.063 cw(c9.152,12.099) 9.116,12.135 9.284,12.303 cw(c9.32,12.267) 9.356,12.303 9.631,12.028 ccw(c9.667,12.064) 9.703,12.028 9.908,12.233 10,12.325 10,19.142 IC1.21@11.96,21.101
DAC_G: C19.2 IC2.10 IC3.8 SP2.1 | length 27.5
  Top Layer w0.17: IC3.8 7.325,21.775 v4(8.25,21.775) ; v2(28.675,24.785) 29.26,24.2 IC2.10
  Top Layer w0.2: IC2.10 29.29,25.39 C19.2 SP2.1
  Bottom Layer w0.17: v4(8.25,21.775) 9.225,21.775 13.675,26.225 16.625,26.225 17.4,25.45 25.225,25.45 25.89,24.785 v2(28.675,24.785)
DCO: IC1.22 J1.5 | length 17
  Top Layer w0.17: J1.5 8.33,8.13 8.5,8.3 8.56,8.36 ccw(c8.5,8.42) 8.56,8.48 8.163,8.877 cw(c8.224,8.937) 8.163,8.997 8.284,9.117 cw(c8.344,9.057) 8.404,9.117 8.801,8.721 ccw(c8.861,8.781) 8.921,8.721 9.1,8.9 10.5,10.3 10.5,18.926 IC1.22@12.349,20.775
GND: C2.2 C5.1 C6.1 C7.1 C10.1 C11.2 C12.2 C13.2 C14.2 C15.2 C18.2 C19.1 C20.1 C21.2 C22.2 C23.2 C24.1 C25.1 C26.1 C27.1 C28.2 C29.2 C30.2 C31.1 C32.1 C33.2 C34.2 D1.1 D1.2 IC1.26 IC1.33 IC2.6 IC2.9 IC2.17 IC2.20 IC3.5 IC3.7 J1.3 J1.4 J2.3 J2.4 K1.2 PS1.1 R3.1 R8.2 U2.2 | length 42.4
  Top Layer w0.381: v4(17.525,9.075) C26.1 C27.1 v1(19.275,8.45) ; C32.1 18.225,7.15 v1(18.8,7.15) ; C33.2 21.175,5.675 v1(22.775,5.675)
  Top Layer w0.4: C30.2 v2(4.225,23) ; C28.2 5.35,24.225 v2(5.375,24.25) ; IC3.5 IC3.5@7.3,19.75 ; IC3.7 v4(8.45,21.075) ; v3(10.975,3.475) C34.2 ; v3(11.3,18.05) 11.836,18.586 C11.2 ; v1(11.675,17.15) 11.675,16.2 C31.1 C31.1@11.725,16.2 ; v2(11.95,29.775) 12.412,29.313 12.487,29.313 C23.2 12.395,29.27 12.086,28.961 12.086,28.159 12.083,28.156 12.083,27.948 C22.2 ; v1(12.925,15.6) 12.95,15.625 C5.1 ; C6.1 14.377,16.248 14.323,16.248 14.25,16.175 14.275,16.175 v1(14.275,15.6) ; PS1.1 15.525,11.975 v1(15.55,11.95) ; v1(15.825,15.5) C15.2 ; C2.2 16.295,19.455 v3(16.8,18.95) ; U2.2 16.748,6.979 17.859,6.979 18.125,7.245 C32.1 ; C12.2@16.945,20.236 16.989,20.236 v1(17.45,19.775) ; C13.2 17.064,26.489 v1(17.575,27) ; v1(17.1,11.925) C29.2 ; C18.2 17.739,25.689 v1(18.3,26.25) ; C14.2 18.575,23.05 18.575,23.75 18.775,23.95 18.775,24 18.875,24.1 R3.1 18.9,24.125 v3(18.9,24.775) ; C20.1 v1(21.975,27.325) ; R8.2 22.8,26.675 22.85,26.675 22.9,26.725 v1(22.9,27.475) ; C24.1 23.35,8.175 v1(23.375,8.15) ; C21.2 23.825,26.35 23.825,27.175 v1(23.85,27.2) ; v1(24.3,8.175) C25.1 ; IC2.6 29.295,21.675 v3(30.13,21.675) ; IC2.9 29.655,23.59 29.675,23.61 30.51,23.61 v1(30.65,23.75) ; C19.1 30.25,25.4 30.275,25.425 v1(31.05,25.425) ; v3(30.85,16.45) C7.1 C10.1 31.875,17.125 v3(31.875,16.5) ; v3(33.125,14.45) D1.1 D1.2 v3(35.025,14.5) ; v1(35.55,25.575) K1.2@38.425,25.575 ; v1(38.425,15.675) K1.2@38.425,17.075
  Bottom Layer w0.4: v1@12.925,15.575 v1(12.925,15.6)
  other v1: 13.275,21.825 12.6,22.4 13.875,22.525 11.975,23 13.125,23.125 14.5,23.2 12.525,23.675 13.8,23.775 13.125,24.3
  other v4: 1.625,21.725
MOSI: IC3.4 J1.11 | length 9.9
  Top Layer w0.17: IC3.4 2.925,19.725 2.925,15.2 3.575,14.55 5.475,14.55 6.675,15.75 J1.11
  Top Layer w0.25: IC3.4 3.235,19.775 IC3.4@3.335,19.675
NetC1_1: C1.1 R2.1 | length 1.1
  Top Layer w0.2: R2.1 20.325,22.825 C1.1
NetC1_2: C1.2 FB1.2 R1.2 | length 2.8
  Top Layer w0.2: FB1.2@20.325,24.225 21.05,23.5 21.05,23.095 21.27,22.875 C1.2 21.325,22.825 R1.2
NetC3_1: C3.1 R5.1 | length 1
  Top Layer w0.2: C3.1 20.325,19.975 R5.1
NetC3_2: C3.2 FB2.2 R4.2 | length 2.9
  Top Layer w0.2: FB2.2 20.875,19.55 20.875,19.63 C3.2@21.095,19.85 ; C3.2 C3.2@21.095,19.85 ; R4.2 21.225,20.8 21.225,19.98 C3.2@21.095,19.85
NetC4_1: C4.1 IC1.31 R2.2 | length 3.6
  Top Layer w0.2: IC1.31 15.956,22.544 16.525,21.975 17.275,21.975 17.45,21.8 C4.1 19.2,21.8 R2.2
NetC4_2: C4.2 IC1.30 R5.2 | length 4.2
  Top Layer w0.2: IC1.30 15.669,22.174 16.093,21.75 16.298,21.75 16.548,21.5 16.8,21.5 17.4,20.9 C4.2 19.15,20.9 R5.2
NetC5_2: C5.2 C6.2 IC1.25 | length 4
  Top Layer w0.2: IC1.25 14.032,20.248 14.525,19.755 14.525,18.4 C6.2
  Top Layer w0.4: C5.2 12.95,17.555 13.52,18.125 C6.2
NetC7_2: C7.2 IC2.1 | length 1.7
  Top Layer w0.2: IC2.1 29.31,18.45 30.455,18.45 30.85,18.055 C7.2
NetC8_1: C8.1 FB3.2 | length 1.8
  Top Layer w0.2: C8.1 32.625,24.15 FB3.2
NetC8_2: C8.2 C9.2 C10.2 IC2.2 | length 8.8
  Top Layer w0.2: IC2.2 29.41,18.99 30.332,18.99 30.572,18.75 31.278,18.75 31.459,18.931 31.459,18.934 C9.2@31.825,19.3 ; C9.2 C9.2@31.825,19.3 ; C10.2 C10.2@31.825,18.075 ; C8.2 32.625,21.47 33.175,20.92 33.175,18.675 32.575,18.075 C10.2@31.825,18.075 ; C10.2@31.825,18.075 C9.2@31.825,19.3
NetC9_1: C9.1 R7.2 | length 1.6
  Top Layer w0.2: C9.1 30.93,19.325 31.3,19.695 31.3,19.728 31.772,20.2 31.85,20.2 R7.2
NetC16_1: C16.1 IC2.7 | length 1.5
  Top Layer w0.2: IC2.7 30.685,22.31 C16.1
NetC16_2: C16.2 IC2.5 | length 1.6
  Top Layer w0.2: IC2.5 29.33,21.07 30.35,21.07 30.75,21.47 C16.2
NetC17_1: C17.1 IC2.8 | length 3.3
  Top Layer w0.2: IC2.8@29.329,22.989 IC2.8 29.34,22.9 30.201,22.9 30.451,23.15 31.525,23.15 31.675,23 31.675,22.425 31.65,22.4 C17.1
NetC17_2: C17.2 IC2.4 R7.1 | length 3.1
  Top Layer w0.2: IC2.4 30.94,20.39 R7.1 31,20.4 31.2,20.6 31.2,20.65 31.455,20.905 31.455,21.255 C17.2
NetC18_1: C18.1 IC1.2 | length 1.6
  Top Layer w0.2: IC1.2 15.788,24.213 16.275,24.7 16.59,24.7 16.98,25.09 C18.1
NetC20_2: C20.2 IC2.12 R8.1 | length 3.9
  Top Layer w0.2: C20.2 R8.1 22.775,25.35 22.775,23.775 22.975,23.575 23.825,23.575 23.85,23.6 IC2.12
NetC32_2: C32.2 U2.4 | length 1.4
  Top Layer w0.4: U2.4 16.748,8.221 18.054,8.221 C32.2
NetD1_3: D1.3 FB3.1 U1.3 | length 6.6
  Top Layer w0.2: D1.3 34.175,17.85 U1.3 34.2,22.55 34.2,23.5 34.45,23.75 34.45,24.125 34.4,24.175 FB3.1
NetIC1_28: IC1.28 R3.2 | length 9.7
  Top Layer w0.17: IC1.28 15.029,21.396 v4(15.35,21.075) ; v4(17.325,24) 17.725,24 R3.2
  Bottom Layer w0.17: v4(15.35,21.075) 15.775,21.5 15.775,24.3 15,25.075 15,25.425 15.475,25.9 16.3,25.9 17.325,24.875 v4(17.325,24)
NetIC2_13: IC2.13 R11.2 | length 9.5
  Top Layer w0.2: IC2.13 26.15,22.95 26.7,22.4 R11.2
NetIC2_14: IC2.14 R10.2 | length 8
  Top Layer w0.2: IC2.14 25.365,22.31 25.7,21.975 R10.2
NetIC2_18: IC2.18 R9.2 | length 4.1
  Top Layer w0.2: R9.2 22.175,16.975 22.375,17.175 22.375,17.225 22.575,17.425 22.575,19.375 22.9,19.7 23.76,19.7 23.785,19.725 23.81,19.7 IC2.18
NetIC2_19: IC2.19 R6.2 | length 4.9
  Top Layer w0.2: R6.2 22.125,15.95 22.758,15.95 22.875,16.067 22.875,18.925 23.075,19.125 23.845,19.125 IC2.19 IC2.19@23.74,18.99
NetK1_1: K1.1 U1.1 | length 3.6
  Top Layer w0.2: U1.1 37.175,22.125 37.975,21.325 K1.1
SCLK: IC3.3 J1.10 | length 10
  Top Layer w0.17: IC3.3 1.95,20.425 1.65,20.125 1.65,14.925 3.185,13.39 4.205,13.39 J1.10
VCM: C2.1 C21.1 IC1.27 IC2.11 SP1.1 | length 25
  Top Layer w0.2: C21.1 23.85,25.43 24.07,25.65 24.4,25.65 25.047,26.297 25.047,26.872 SP1.1
  Top Layer w0.25: IC1.27 14.668,21.007 v4(15.137,20.538) 15.605,20.07 C2.1 ; C21.1 23.9,25.375 v4@23.9,24.823 ; IC2.11 23.9,24.27 v4@23.9,24.823 ; v4(23.895,24.818) v4@23.9,24.823
  Bottom Layer w0.25: v4(15.137,20.538) 12.613,20.538 12.1,20.025 12.1,18.725 13.5,17.325 16.402,17.325 v4(23.895,24.818)
VOH: FB1.1 IC2.15 R1.1 | length 4
  Top Layer w0.2: FB1.1@22.075,24.225 22.075,23.35 22.425,23 R1.1 22.5,21.8 22.925,21.8 23.05,21.675 23.855,21.675 IC2.15
VOL: FB2.1 IC2.16 R4.1 | length 4.2
  Top Layer w0.2: FB2.1 21.75,18.675 21.75,19.45 22.4,20.1 R4.1 22.555,21.03 IC2.16
pads on no net: IC1.4 IC1.5 IC1.6 IC1.7 IC1.8 IC1.9 IC1.10 IC1.23 IC3.6 J2.12 U1.2 U2.3 U2.6 U2.7

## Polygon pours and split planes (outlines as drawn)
GND on Bottom Layer "Bottom Layer-GND" (solid, pour order 2): 1.25,0.6 0.6,1.25 0.599,1.3 0.526,41.75 1.425,42.65 42.3,42.65 42.663,42.287 42.713,1.362 41.95,0.6
GND on Top Layer "Top Layer-GND" (solid, pour order 0): 1.95,0.65 0.822,1.903 0.727,41.95 1.45,42.7 42.275,42.7 42.7,42.3 42.7,1.35 42,0.65
GND on Int1 (GND) (split plane): 41.474,42.67 41.525,42.665 41.534,42.665 41.542,42.666 41.55,42.667 41.676,42.658 41.8,42.634 41.92,42.593 42.033,42.537 42.139,42.467 42.234,42.384 42.317,42.289 42.387,42.183 42.443,42.07 42.484,41.95 42.508,41.826 42.515,41.728 42.515,41.725 42.515,1.5 42.516,1.483 42.517,1.475 42.508,1.349 42.484,1.225 42.443,1.105 42.387,0.992 42.317,0.886 42.234,0.791 42.139,0.708 42.033,0.638 41.92,0.582 41.8,0.541 41.676,0.517 41.578,0.51 41.575,0.51 41.55,0.51 1.5,0.51 1.491,0.51 1.483,0.509 1.475,0.508 1.349,0.517 1.225,0.541 1.105,0.582 0.992,0.638 0.886,0.708 0.791,0.791 0.708,0.886 0.638,0.992 0.582,1.105 0.541,1.225 0.517,1.349 0.51,1.447 0.51,1.45 0.51,41.675 0.51,41.684 0.509,41.692 0.508,41.7 0.517,41.826 0.541,41.95 0.582,42.07 0.638,42.183 0.708,42.289 0.791,42.384 0.886,42.467 0.992,42.537 1.105,42.593 1.225,42.634 1.349,42.658 1.447,42.665 1.45,42.665 1.459,42.665 1.501,42.67
GND on Int2 (GND) (split plane): 41.474,42.67 41.525,42.665 41.534,42.665 41.542,42.666 41.55,42.667 41.676,42.658 41.8,42.634 41.92,42.593 42.033,42.537 42.139,42.467 42.234,42.384 42.317,42.289 42.387,42.183 42.443,42.07 42.484,41.95 42.508,41.826 42.515,41.728 42.515,41.725 42.515,1.5 42.516,1.483 42.517,1.475 42.508,1.349 42.484,1.225 42.443,1.105 42.387,0.992 42.317,0.886 42.234,0.791 42.139,0.708 42.033,0.638 41.92,0.582 41.8,0.541 41.676,0.517 41.578,0.51 41.575,0.51 41.55,0.51 1.5,0.51 1.491,0.51 1.483,0.509 1.475,0.508 1.349,0.517 1.225,0.541 1.105,0.582 0.992,0.638 0.886,0.708 0.791,0.791 0.708,0.886 0.638,0.992 0.582,1.105 0.541,1.225 0.517,1.349 0.51,1.447 0.51,1.45 0.51,41.675 0.51,41.684 0.509,41.692 0.508,41.7 0.517,41.826 0.541,41.95 0.582,42.07 0.638,42.183 0.708,42.289 0.791,42.384 0.886,42.467 0.992,42.537 1.105,42.593 1.225,42.634 1.349,42.658 1.447,42.665 1.45,42.665 1.459,42.665 1.501,42.67

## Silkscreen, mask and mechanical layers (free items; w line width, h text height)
Top Overlay:
  text "AFE v1.0" at 26.55,39.925 h1.5
  text "@kelu124" at 35.75,5.025 h0.7
  text "http://un0rick.cc/goodies/afe" at 22.15,2.775 h0.7
Bottom Overlay:
  text "VGA:AD8331ARQZ" at 29.7,36.75 h0.7
  text "ADC:AD9629BCPZ-65" at 30.5,35.075 h0.7
  text "DAC:MCP4812-E_MS" at 30.5,33.425 h0.7
Mechanical 1:
  lines w0.4: 1.45,43.175 ccw(c1.475,41.7) 0,41.675 0,1.45 ccw(c1.475,1.475) 1.5,0 41.55,0 ; 1.45,43.18 41.525,43.18 ; 4.225,88.4 cw(c5.7,88.425) 5.675,89.9 ; 41.525,43.175 cw(c41.55,41.7) 43.025,41.725 43.025,1.5 cw(c41.55,1.475) 41.575,0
